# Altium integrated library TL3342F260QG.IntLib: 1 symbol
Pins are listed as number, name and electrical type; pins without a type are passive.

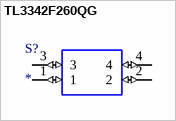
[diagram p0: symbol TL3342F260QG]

## TL3342F260QG
designator S?
Tactile Switch SPST-NO Top Actuated Surface Mount; MF: E-Switch; MP: TL3342F260QG
footprint TL3342F260QG
pins: 1 (io), 2 (io), 3 (io), 4 (io)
